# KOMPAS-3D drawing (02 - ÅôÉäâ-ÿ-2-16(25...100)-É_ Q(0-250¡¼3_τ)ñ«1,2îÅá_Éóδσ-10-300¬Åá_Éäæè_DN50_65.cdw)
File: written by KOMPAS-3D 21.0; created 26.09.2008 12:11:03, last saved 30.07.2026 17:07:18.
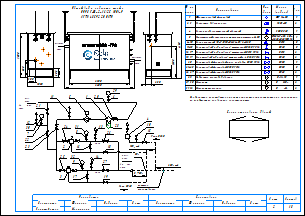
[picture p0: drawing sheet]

Sheets 1-2: A3, landscape

Document properties: Наименование: Макро:21; Автор: RaskoAdmin; Форматы листов документа: 2xA3; Полное имя файла: \\ur38nt01\Departments\КТО\КБ ПУРДГ\Заявки\Прайс-лист на типовые шкафы ГРПШ\ПУРДГ_стандарт_30_04_2026\ПУРДГ с РДСК\ПУРДГ-Ш-2-16(25...100)-Р_ Q(0-250нм3_ч)до1,2МПа_Рвых-10-300кПа_РДСК_DN50_65.cdw

Title block, sheet 1: Наименование: Пункт учета газа / ПУГ-Ш-400-Р / ЛГТИ.485922.001ТУ; designation: ЛГТИ.03.4411141; sheet number: 1; Количество листов документа: 2; organisation: ООО "ЭЛЬСТЕР Газэлектроника"; Форматы листов документа: A3; stored path: C:\Рабочие документы\Компас\ПУГ\Схема.cdw; Разработал: Устинов; Проверил: Кошкин; Утвердил: Кошкин
Title block, sheet 2: sheet number: 2; stored path: D:\Рабочие документы\Заявки\ПУРДГ\ПУРДГ-ШУЭО-2-100-Р 4411220.cdw; designation, second copy: ЛГТИ.03.4411141-

Views: Вид 1, Вид 2
Referenced files: wcvoit.frw
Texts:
  Normal
  № на
  схеме
  Усл.
  обозн.
  Марка
  (модель)
  Кол.
  Фильтр газовый фланцевый
  ФГ 16-50
  Регулятор давления газа
  РДСК-50
  Клапан предохранительный сбросной
  КПС DN20
  Измерительный комплекс с ротационным счетчиком Ду50
  СГ-ЭК-Р-(0,2...2,0)-
  Кран кнопочный VE-РАСКО-НЗ-1,6-G1/2-М20
  DN15
  Кран шаровой "под приварку" штуцерный DN20 PN16
  DN20
  Кран шаровой "под приварку" штуцерный DN15 PN16
  Кран шаровой "под приварку" штуцерный п/п DN20 PN16
  Кран шаровой фланцевый с мех. приводом DN50 PN16
  Кран шаровой фланцевый DN50 PN16
  Кран шаровой фланцевый DN65 PN16
  DN50
  DN65
  Индикатор перепада давления
  Манометр
  Манометр-напоромер
  Delta 15
  0...     МПа
  0...     кПа
  Общий вид и габариты шкафа
  ПУРДГ-Ш-2-16(25...100)-Р
  Выход газа
  Вход газа
  logo-rasko-ge.png
  DN 1
  местное
  сопротивление
  Римп DN20
  Выход
  газа
  Р=     кПа
  Вход
  Р=       МПа
  PDI
  Схема открывания дверей
  Предприятие изготовитель может заменять комплектующие на аналогичные,
  не ухудшающие заявленных характеристик.
  Должность
  Конструктор
  Фамилия
  Подпись
  Дата
  Согласовано
  Максимкин
  Лист
  Листов
  POLYLINE_STYLE_0.18_RGB_0_0_0
  POLYLINE_STYLE_0.50_RGB_0_0_0
  POLYLINE_STYLE_0.34_RGB_0_0_0
  PHANTOM_RGB_0_0_0_SC_1_THICK_0.18
  K5LT_THIN_RGB_0_0_0_THICK_0.18
  K5LT32769_RGB_0_0_0_THICK_0.18
  K5LT12_RGB_0_0_0_SC_1_THICK_0.18
  K5LT_DASHED_RGB_0_0_0_SC_1_THICK_0.18
  ACISOTGL_RGB_0_0_0_SC_0.8_THICK_0.25
  CONTINUOUS_RGB_0_127_31_THICK_0.3
  CONTINUOUS_RGB_0_0_255_THICK_0.35
  CONTINUOUS_RGB_255_0_0_THICK_0.35
  POLYLINE_STYLE_0.25_RGB_0_0_0
  CONTINUOUS_RGB_0_0_0_THICK_0.5
  POLYLINE_STYLE_0.35_RGB_0_0_255
  CONTINUOUS_RGB_0_0_0_THICK_0.4
  CONTINUOUS_RGB_0_0_0_THICK_0.35
  НЕВИДИМАЯ_RGB_0_0_0_SC_0.3_THICK_0.25
  СONTINUOUS_RGB_0_0_0_THICK_0.25
  ОСЕВАЯ2_RGB_248_153_30_SC_0.3_THICK_0.25
  Без оформления
Dimensions and other numbers on the sheet: 1; 2, 3; 2; 4; 5; 6-10; 11-15; 16, 17; 18, 19; 20; 21-25; 26, 27; 28; 29, 30; 31, 32; 1500; 250; 300; 1050; 550; 305; 2300; 4130; 2000; 2600; 5,,,7DN 1; 7; 30; 12; 21; 22; 23; 11; 6; 29; 24; 31; 8; 16; 13; 26; 18; 10; 15; 25; 32; 9; 3; 17; 14; 27; 19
